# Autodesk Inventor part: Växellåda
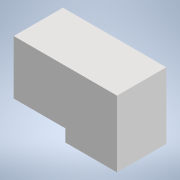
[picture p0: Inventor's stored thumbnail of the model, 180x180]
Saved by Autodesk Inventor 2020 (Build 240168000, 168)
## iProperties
Created: 2019-06
Part Number: Växellåda
Material: Acetal Resin, Black
Document SubType Name: Modeling
Designer: cl
Density: 1.425 g/cm^3
Appearance: Smooth - Black
Author: cl
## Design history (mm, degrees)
sketch "Sketch1"
  geometry: L1 (0, 0)-(210, 0); L2 (0, 0)-(0, -110); L3 (0, -110)-(105, -110); L4 (105, -110)-(105, -135); L5 (105, -135)-(210, -135); L6 (210, -135)-(210, 0)
  constraints: 12 end point, 3 perpendicular, 1 horizontal, 1 vertical
  dimensions: "d0" = 210 distance of L1.start L1.end; "d1" = 110 distance of L1.start L2.end; "d2" = 105 distance of L2.end L3.end; "d3" = 25 distance of L3.end L4.end; "d4" = 105 distance of L4.end L5.end
extrude "Extrusion1" new body sketch "Sketch1" distance "d5" = 100; taper "d6" = 0 deg
fillet "Fillet1" dims "d7" = 5
body "Solid1"
